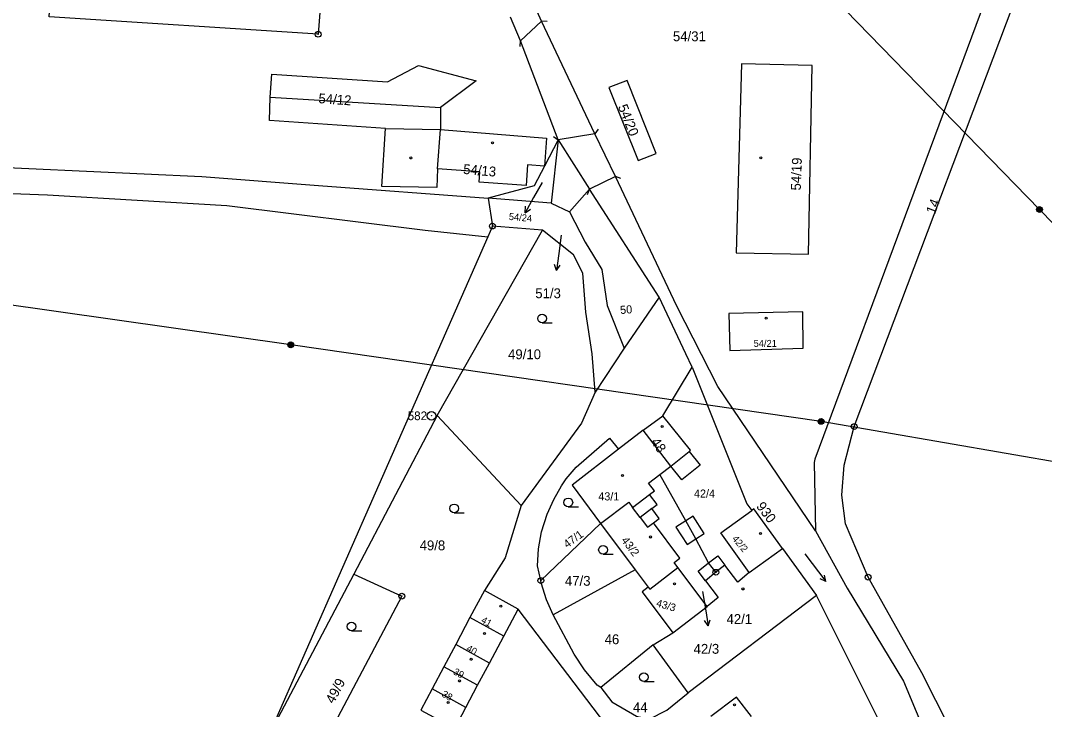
# Model space of a CAD drawing. Extents: x -504988 to -494607, y -1123820 to -1114018.
# Drawn here: x -501341.4 to -501164.5, y -1121268.8 to -1121149.7 of the extents above; entities that cross this region are included whole.
import ezdxf

# ---------------------------------------------------------------- set-up
doc = ezdxf.new("R2010")
doc.units = 0
for name, color, linetype in [('Hranice parcel', 7, 'Continuous'), ('Parcelní čísla', 7, 'Continuous'), ('Pop  PČ popisy', 7, 'Continuous'), ('Poz předměty', 7, 'Continuous'), ('Vnitřní kresba', 7, 'Continuous'), ('Značky bodu BP', 7, 'Continuous'), ('Značky budov', 7, 'Continuous'), ('Značky kultur', 7, 'Continuous')]:
    doc.layers.add(name, color=color, linetype=linetype)

msp = doc.modelspace()

# ---------------------------------------------------------------- linework, layer by layer
at = {"layer": 'Hranice parcel'}
for p, q in [((-501251.43, -1121149.84), (-501253.15, -1121145.89)), ((-501255.05, -1121153.19), (-501256.8, -1121149.14)), ((-501242.24, -1121169.27), (-501251.43, -1121149.84)), ((-501248.52, -1121170.32), (-501255.05, -1121153.19)), ((-501298.31, -1121162.96), (-501268.86, -1121164.72)), ((-501248.52, -1121170.32), (-501243.14, -1121178.84)), ((-501238.65, -1121176.65), (-501242.24, -1121169.27)), ((-501231.12, -1121197.51), (-501243.14, -1121178.84)), ((-501260.63, -1121180.43), (-501259.9, -1121185.23)), ((-501259.9, -1121185.23), (-501260.72, -1121187.1)), ((-501260.72, -1121187.1), (-501298.5, -1121273.15)), ((-501231.12, -1121197.51), (-501237.15, -1121206.35)), ((-501237.15, -1121206.35), (-501242.14, -1121213.96)), ((-501230.48, -1121218.01), (-501225.41, -1121209.59)), ((-501233.85, -1121220.47), (-501230.48, -1121218.01)), ((-501233.85, -1121220.47), (-501238.13, -1121223.8)), ((-501229.08, -1121226.7), (-501233.85, -1121220.47)), ((-501230.99, -1121228.17), (-501229.08, -1121226.7)), ((-501251.54, -1121246.49), (-501241.21, -1121236.65)), ((-501241.21, -1121236.65), (-501235.23, -1121244.64)), ((-501215.55, -1121245.08), (-501209.8, -1121240.96)), ((-501209.8, -1121240.96), (-501203.94, -1121249.08)), ((-501235.23, -1121244.64), (-501249.43, -1121252.44)), ((-501235.23, -1121244.64), (-501233.01, -1121247.65)), ((-501222.82, -1121250.99), (-501227.87, -1121244.26)), ((-501221.3, -1121245.06), (-501223.1, -1121246.52)), ((-501219.76, -1121243.81), (-501221.3, -1121245.06)), ((-501283.87, -1121245.38), (-501297.57, -1121271.38)), ((-501261.28, -1121248.18), (-501263.79, -1121252.9)), ((-501203.94, -1121249.08), (-501226.1, -1121265.87)), ((-501189.3, -1121278.22), (-501203.94, -1121249.08)), ((-501228.75, -1121255.5), (-501222.82, -1121250.99)), ((-501263.79, -1121252.9), (-501266.25, -1121257.52)), ((-501257.95, -1121256.11), (-501263.79, -1121252.9)), ((-501232.16, -1121257.57), (-501228.75, -1121255.5)), ((-501266.25, -1121257.52), (-501268.31, -1121261.4)), ((-501260.42, -1121260.75), (-501266.25, -1121257.52)), ((-501260.42, -1121260.75), (-501257.95, -1121256.11)), ((-501232.16, -1121257.57), (-501241.2, -1121264.95)), ((-501226.1, -1121265.87), (-501232.16, -1121257.57)), ((-501262.46, -1121264.59), (-501260.42, -1121260.75)), ((-501268.31, -1121261.4), (-501270.34, -1121265.22)), ((-501262.46, -1121264.59), (-501268.31, -1121261.4)), ((-501264.5, -1121268.42), (-501262.46, -1121264.59)), ((-501264.5, -1121268.42), (-501270.34, -1121265.22))]:
    msp.add_line(p, q, dxfattribs=at)
for points in [[(-501149.92, -1121321.68), (-501163.66, -1121307.57), (-501169.62, -1121297.33), (-501176.8, -1121276.99), (-501180.86, -1121271.98), (-501185.74, -1121262.45), (-501194.99, -1121245.9), (-501198.92, -1121236.67), (-501199.55, -1121231.72), (-501199.14, -1121226.57), (-501197.4, -1121219.88), (-501165.31, -1121134.77), (-501163.84, -1121129.08), (-501163.82, -1121124.26)], [(-501288.4, -1121130.84), (-501290.01, -1121152.09), (-501336.48, -1121149.05), (-501335.42, -1121132.73)], [(-501169.98, -1121133.31), (-501204.19, -1121225.49), (-501204.3, -1121226.11), (-501204.08, -1121237.88)], [(-501298.31, -1121162.96), (-501298.03, -1121158.97), (-501278.04, -1121160.32), (-501272.69, -1121157.46), (-501262.74, -1121160.1), (-501268.86, -1121164.72)], [(-501205.31, -1121190.11), (-501204.64, -1121157.48), (-501216.85, -1121157.2), (-501217.77, -1121189.84), (-501205.31, -1121190.11)], [(-501231.6, -1121172.68), (-501236.62, -1121160.08), (-501239.77, -1121161.28), (-501234.73, -1121173.92), (-501231.6, -1121172.68)], [(-501268.86, -1121164.72), (-501268.88, -1121168.53), (-501250.56, -1121170.06), (-501250.9, -1121174.86), (-501253.85, -1121174.65), (-501254.1, -1121178.22), (-501262.2, -1121177.66), (-501262.07, -1121175.84), (-501269.37, -1121175.34), (-501269.53, -1121178.54), (-501279.03, -1121178.39), (-501278.4, -1121168.39), (-501298.42, -1121166.98), (-501298.31, -1121162.96)], [(-501462.67, -1121168.87), (-501458.24, -1121169.62), (-501453.18, -1121170), (-501369.91, -1121173.9), (-501310.1, -1121176.67), (-501289.93, -1121178.21), (-501260.63, -1121180.43)], [(-501248.52, -1121170.32), (-501249.74, -1121181.26), (-501260.63, -1121180.43)], [(-501248.52, -1121170.32), (-501250.9, -1121174.86), (-501252.71, -1121178.3), (-501260.63, -1121180.43)], [(-501462.77, -1121173.37), (-501457.64, -1121173.88), (-501418.64, -1121176.38), (-501379.92, -1121178.21), (-501336.76, -1121179.84), (-501305.77, -1121181.65), (-501271.52, -1121185.95), (-501260.72, -1121187.1)], [(-501204.08, -1121237.88), (-501220.99, -1121212.93), (-501228.02, -1121199.06), (-501238.65, -1121176.65)], [(-501243.14, -1121178.84), (-501246.58, -1121182.74), (-501243.9, -1121188.02), (-501241, -1121192.74), (-501240.07, -1121198.95), (-501237.15, -1121206.35)], [(-501242.14, -1121213.96), (-501242.68, -1121207.28), (-501243.76, -1121200.13), (-501244.3, -1121193.38), (-501245.9, -1121190.22), (-501251.27, -1121185.93), (-501259.9, -1121185.23)], [(-501225.41, -1121209.59), (-501226.47, -1121207.33), (-501231.12, -1121197.51)], [(-501206.28, -1121200.02), (-501219.06, -1121200.36), (-501218.89, -1121206.71), (-501206.23, -1121206.32), (-501206.28, -1121200.02)], [(-501225.41, -1121209.59), (-501215.94, -1121233.24), (-501215.09, -1121234.36)], [(-501242.14, -1121213.96), (-501244.51, -1121219.28), (-501254.95, -1121233.49)], [(-501254.95, -1121233.49), (-501269.44, -1121217.98), (-501283.87, -1121245.38)], [(-501229.08, -1121226.7), (-501225.92, -1121224.16), (-501225.69, -1121223.98), (-501230.48, -1121218.01)], [(-501251.54, -1121246.49), (-501252.1, -1121243.95), (-501251.96, -1121241), (-501251.44, -1121238.04), (-501250.44, -1121235.03), (-501249.3, -1121232.46), (-501247.99, -1121230.14), (-501247.16, -1121228.91), (-501245.45, -1121226.89), (-501239.69, -1121221.9), (-501238.13, -1121223.8)], [(-501238.13, -1121223.8), (-501246.1, -1121230), (-501241.21, -1121236.65)], [(-501232.75, -1121231.63), (-501231.91, -1121231), (-501232.94, -1121229.63), (-501230.99, -1121228.17)], [(-501221.3, -1121245.06), (-501222.56, -1121243.41), (-501224.78, -1121239.27), (-501226.51, -1121236.18), (-501230.99, -1121228.17)], [(-501241.21, -1121236.65), (-501236.35, -1121232.96), (-501235.7, -1121233.84), (-501232.75, -1121231.63)], [(-501227.87, -1121244.26), (-501228.53, -1121243.38), (-501227.53, -1121242.63), (-501232.1, -1121236.53), (-501231.09, -1121235.77), (-501232.38, -1121234.05), (-501231.45, -1121233.36), (-501232.75, -1121231.63)], [(-501254.95, -1121233.49), (-501257.72, -1121242.54), (-501261.28, -1121248.18)], [(-501215.55, -1121245.08), (-501220.47, -1121238.26), (-501215.09, -1121234.36)], [(-501209.8, -1121240.96), (-501214.74, -1121234.1), (-501215.09, -1121234.36)], [(-501204.08, -1121237.88), (-501198.63, -1121247.81), (-501188.86, -1121263.88), (-501182.59, -1121278.93), (-501154.99, -1121328.94)], [(-501233.01, -1121247.65), (-501232.73, -1121247.98), (-501227.87, -1121244.26)], [(-501215.55, -1121245.08), (-501217.48, -1121246.78), (-501219.76, -1121243.81)], [(-501283.87, -1121245.38), (-501275.55, -1121249.18), (-501289.28, -1121275.13)], [(-501249.43, -1121252.44), (-501250.55, -1121249.81), (-501251.46, -1121246.86), (-501251.54, -1121246.49)], [(-501223.1, -1121246.52), (-501220.91, -1121249.39), (-501222.82, -1121250.99)], [(-501257.95, -1121256.11), (-501255.46, -1121251.44), (-501261.28, -1121248.18)], [(-501233.01, -1121247.65), (-501234.04, -1121248.42), (-501228.75, -1121255.5)], [(-501241.2, -1121264.95), (-501241.78, -1121264.56), (-501244.01, -1121261.92), (-501245.76, -1121259.2), (-501249.43, -1121252.44)], [(-501270.34, -1121265.22), (-501272.29, -1121268.89), (-501270.77, -1121269.71)], [(-501241.2, -1121264.95), (-501239.26, -1121267.42), (-501235, -1121269.95), (-501232.84, -1121270.44), (-501229.8, -1121268.86), (-501226.1, -1121265.87)], [(-501215.16, -1121270), (-501217.74, -1121266.63), (-501222.18, -1121269.98)], [(-501270.77, -1121269.71), (-501266.42, -1121272.04), (-501264.5, -1121268.42)]]:
    msp.add_lwpolyline(points, dxfattribs=at)
at = {"layer": 'Pop  PČ popisy'}
for p, q in [((-501251.32, -1121177.68), (-501252.79, -1121180.29)), ((-501252.79, -1121180.29), (-501254.24, -1121182.92)), ((-501254.24, -1121182.92), (-501254.2, -1121181.8)), ((-501254.24, -1121182.92), (-501253.32, -1121182.28)), ((-501248, -1121186.81), (-501248.42, -1121189.94)), ((-501248.42, -1121189.94), (-501248.84, -1121192.91)), ((-501248.84, -1121192.91), (-501249.19, -1121191.85)), ((-501248.84, -1121192.91), (-501248.2, -1121191.99)), ((-501223.59, -1121248.4), (-501223.1, -1121251.36)), ((-501223.1, -1121251.36), (-501222.63, -1121254.32)), ((-501222.63, -1121254.32), (-501223.28, -1121253.41)), ((-501222.63, -1121254.32), (-501222.29, -1121253.26))]:
    msp.add_line(p, q, dxfattribs=at)
at = {"layer": 'Poz předměty'}
for p, q in [((-501165.39, -1121182.36), (-501206.24, -1121140.35)), ((-501114.82, -1121234.34), (-501165.39, -1121182.36)), ((-501294.74, -1121205.75), (-501387.81, -1121192.52)), ((-501203.12, -1121218.99), (-501294.74, -1121205.75)), ((-501114.82, -1121234.34), (-501203.12, -1121218.99))]:
    msp.add_line(p, q, dxfattribs=at)
for centre, radius in [((-501165.39, -1121182.36), 0.5), ((-501165.39, -1121182.36), 0.4), ((-501165.39, -1121182.36), 0.3), ((-501165.39, -1121182.36), 0.2), ((-501165.39, -1121182.36), 0.1), ((-501294.74, -1121205.75), 0.5), ((-501294.74, -1121205.75), 0.4), ((-501294.74, -1121205.75), 0.3), ((-501294.74, -1121205.75), 0.2), ((-501294.74, -1121205.75), 0.1), ((-501203.12, -1121218.99), 0.5), ((-501203.12, -1121218.99), 0.4), ((-501203.12, -1121218.99), 0.3), ((-501203.12, -1121218.99), 0.2), ((-501203.12, -1121218.99), 0.1)]:
    msp.add_circle(centre, radius, dxfattribs=at)
at = {"layer": 'Vnitřní kresba'}
for p, q in [((-501251.43, -1121149.84), (-501255.05, -1121153.19)), ((-501250.43, -1121149.88), (-501251.43, -1121149.84)), ((-501255.09, -1121154.19), (-501255.05, -1121153.19)), ((-501278.4, -1121168.39), (-501268.88, -1121168.53)), ((-501269.37, -1121175.34), (-501268.88, -1121168.53)), ((-501241.65, -1121168.46), (-501242.24, -1121169.27)), ((-501249.33, -1121169.73), (-501248.52, -1121170.32)), ((-501242.24, -1121169.27), (-501248.52, -1121170.32)), ((-501238.65, -1121176.65), (-501243.14, -1121178.84)), ((-501237.7, -1121176.98), (-501238.65, -1121176.65)), ((-501243.47, -1121179.79), (-501243.14, -1121178.84)), ((-501249.74, -1121181.26), (-501246.58, -1121182.74)), ((-501269.44, -1121217.98), (-501251.27, -1121185.93)), ((-501225.92, -1121224.16), (-501224.01, -1121226.54)), ((-501227.17, -1121229.08), (-501229.08, -1121226.7)), ((-501224.01, -1121226.54), (-501227.17, -1121229.08)), ((-501234.4, -1121235.57), (-501235.7, -1121233.84)), ((-501232.38, -1121234.05), (-501234.4, -1121235.57)), ((-501234.4, -1121235.57), (-501233.11, -1121237.28)), ((-501226.51, -1121236.18), (-501228.19, -1121237.27)), ((-501225.25, -1121235.37), (-501226.51, -1121236.18)), ((-501223.32, -1121238.33), (-501225.25, -1121235.37)), ((-501233.11, -1121237.28), (-501232.1, -1121236.53)), ((-501228.19, -1121237.27), (-501226.27, -1121240.23)), ((-501226.27, -1121240.23), (-501224.78, -1121239.27)), ((-501224.78, -1121239.27), (-501223.32, -1121238.33)), ((-501224.35, -1121244.89), (-501222.56, -1121243.41)), ((-501222.56, -1121243.41), (-501220.99, -1121242.19)), ((-501220.99, -1121242.19), (-501219.76, -1121243.81)), ((-501223.1, -1121246.52), (-501224.35, -1121244.89)), ((-501238.28, -1121273.99), (-501255.46, -1121251.44))]:
    msp.add_line(p, q, dxfattribs=at)
at = {"layer": 'Značky bodu BP'}
for centre, radius in [((-501290.01, -1121152.09), 0.5), ((-501290.01, -1121152.09), 0.0303), ((-501259.9, -1121185.23), 0.5), ((-501259.9, -1121185.23), 0.0303), ((-501270.44, -1121218.02), 0.75), ((-501270.44, -1121218.02), 0.03), ((-501197.4, -1121219.88), 0.5), ((-501197.4, -1121219.88), 0.0303), ((-501221.3, -1121245.06), 0.5), ((-501221.3, -1121245.06), 0.0303), ((-501251.54, -1121246.49), 0.5), ((-501251.54, -1121246.49), 0.0303), ((-501194.99, -1121245.9), 0.5), ((-501194.99, -1121245.9), 0.0303), ((-501275.55, -1121249.18), 0.5), ((-501275.55, -1121249.18), 0.0303)]:
    msp.add_circle(centre, radius, dxfattribs=at)
at = {"layer": 'Značky budov'}
for centre in [(-501259.88, -1121170.84), (-501273.98, -1121173.46), (-501213.52, -1121173.44), (-501212.62, -1121201.15), (-501230.57, -1121219.87), (-501237.44, -1121228.34), (-501213.59, -1121238.35), (-501232.58, -1121238.96), (-501228.45, -1121247.07), (-501216.62, -1121247.94), (-501258.47, -1121250.91), (-501261.26, -1121255.65), (-501263.59, -1121260.1), (-501265.61, -1121263.84), (-501267.55, -1121267.57), (-501218.08, -1121267.96)]:
    msp.add_circle(centre, 0.175, dxfattribs=at)
at = {"layer": 'Značky kultur'}
for p, q in [((-501251.33, -1121201.94), (-501249.58, -1121201.94)), ((-501246.79, -1121233.73), (-501245.04, -1121233.73)), ((-501266.51, -1121234.76), (-501264.76, -1121234.76)), ((-501240.8, -1121241.92), (-501239.05, -1121241.92)), ((-501205.93, -1121241.86), (-501202.32, -1121246.66)), ((-501202.32, -1121246.66), (-501203.31, -1121246.18)), ((-501202.32, -1121246.66), (-501202.51, -1121245.57)), ((-501284.24, -1121255.17), (-501282.49, -1121255.17)), ((-501233.74, -1121263.95), (-501231.99, -1121263.95))]:
    msp.add_line(p, q, dxfattribs=at)
for centre in [(-501251.33, -1121201.19), (-501246.79, -1121232.98), (-501266.51, -1121234.01), (-501240.8, -1121241.17), (-501284.24, -1121254.42), (-501233.74, -1121263.2)]:
    msp.add_circle(centre, 0.75, dxfattribs=at)

# ---------------------------------------------------------------- texts
at = {"layer": 'Parcelní čísla'}
for s, height, p in [('54/31', 1.7, (-501228.72, -1121153.28)), ('51/3', 1.7, (-501252.5, -1121197.69)), ('54/21', 1.2, (-501214.78, -1121206.1)), ('49/10', 1.7, (-501257.2, -1121208.23)), ('43/1', 1.4, (-501241.62, -1121232.64)), ('42/4', 1.4, (-501225.09, -1121232.16)), ('49/8', 1.7, (-501272.48, -1121241.26)), ('47/3', 1.7, (-501247.38, -1121247.39)), ('42/1', 1.7, (-501219.46, -1121253.99)), ('46', 1.7, (-501240.52, -1121257.49)), ('42/3', 1.7, (-501225.15, -1121259.14)), ('44', 1.7, (-501235.63, -1121269.26))]:
    msp.add_text(s, height=height, dxfattribs=at).set_placement(p)
for s, height, rotation, p in [('54/12', 1.7, 356, (-501290, -1121163.98)), ('54/20', 1.7, 292, (-501238.26, -1121164.59)), ('54/13', 1.7, 355, (-501265.01, -1121176.2)), ('54/19', 1.7, 88, (-501206.64, -1121179.1)), ('14', 1.7, 69, (-501183.48, -1121183.31)), ('54/24', 1.2, 355, (-501257.11, -1121184.16)), ('50', 1.4, 4, (-501237.79, -1121200.43)), ('48', 1.7, 305, (-501232.61, -1121222.54)), ('930', 1.7, 307, (-501214.42, -1121233.68)), ('47/1', 1.4, 36, (-501246.99, -1121240.95)), ('43/2', 1.4, 307, (-501237.72, -1121239.55)), ('42/2', 1.2, 310, (-501218.58, -1121239.31)), ('43/3', 1.3, 344, (-501231.7, -1121250.93)), ('41', 1.2, 331, (-501261.98, -1121253.68)), ('40', 1.2, 331, (-501264.54, -1121258.56)), ('39', 1.2, 331, (-501266.79, -1121262.59)), ('49/9', 1.7, 62, (-501287.34, -1121267.89)), ('38', 1.2, 331, (-501268.77, -1121266.46))]:
    msp.add_text(s, height=height, rotation=rotation, dxfattribs=at).set_placement(p)
at = {"layer": 'Značky bodu BP'}
msp.add_text('582', height=1.5, dxfattribs=at).set_placement((-501274.54, -1121218.77))

doc.saveas('drawing.dxf')
